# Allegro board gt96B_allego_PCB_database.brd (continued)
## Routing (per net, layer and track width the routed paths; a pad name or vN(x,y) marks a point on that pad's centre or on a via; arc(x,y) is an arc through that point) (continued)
VBATTERY:
  vias: v2(40.59,27.44)
VBUS_USBA_1: length 3.8
  TOP w0.9: 70.85,14.45 70.85,12.73 71.95,11.63 J6.1
VBUS_USBA_2: length 2.1
  TOP w0.9: 51.45,12.73 52.55,11.63 J8.1
1P8_ISET: length 2
  TOP w0.1: v2(41.9,45.75) 42.15,45.5 R145.1 42.15,44.87 U24.C1
1P8_OUT_OCFLAG_N: length 4.2
  TOP w0.1: TP42.1 44.8,41.39 44.8,44.21 U24.A1
5P0V_BOOT: length 5.9
  BOTTOM w0.2: C148.1 v1(65.88,23.19)
  BOTTOM w0.25: U21.1 68.82,21.64 68.37,22.08 67.01,22.08 65.89,23.19 v1(65.88,23.19)
5P0V_COMP: length 2.8
  BOTTOM w0.2: v3(64.72,18.48) U21.6
  BOTTOM w0.35: C151.1 C150.1 63.39,19.09 U21.6
5P0V_EN: length 3.4
  BOTTOM w0.2: U21.3 69.63,19.09 69.43,18.89 v3(69.43,18.48)
  BOTTOM w0.35: U21.3 70.12,19.1 R78.2 R79.1
5P0V_PH:
  vias: v2(63.97,22.59)
5P0V_SENSE: length 3.1
  BOTTOM w0.3: v3(63.1,16.53) 63.35,16.78 63.39,16.78 63.67,17.06 ; 63.67,17.06 R82.1 ; 63.67,17.06 63.92,17.06
  BOTTOM w0.35: R82.1 63.74,17.82 U21.5
5P0V_SS: length 2.4
  BOTTOM w0.2: v3(70.09,16.94) 70.12,16.97 U21.4
  BOTTOM w0.35: U21.4 71.17,17.82 C149.1
+1P1V_SW: length 2.1
  TOP w0.5: L5.1 64.8,38.62 65.67,37.75 v2(65.67,37.59)
+1P8V_BREAKOUT: length 0.8
  TOP w0.25: C144.1 43.64,45.64 U24.B1
  vias: v1(44.03,46.15)
+SYS_DCIN:
  vias: v1(42.91,52.74) v1(42.91,51.81) v1(43.05,51.33) v1(43.09,53.21) v1(43.09,52.28) v1(44.93,52.81) v1(44.91,51.87) v1(45.09,53.28) v1(45.09,52.33) v1(46.91,52.46) v1(46.91,51.53) v1(47.09,52) v1(47.1,51.07) v1(49.47,51.96) v1(49.81,52.34) v1(49.97,51.87) v1(50.31,52.23) v1(59.68,51.79) v1(59.93,51.31) v1(60.18,51.79) v1(60.39,51.13) v1(60.63,51.57) v1(60.9,51.02) v1(61.03,52.45) v1(61.14,52.93) v1(61.14,51.96) v1(61.14,51.46) v1(61.21,50.34) v1(61.44,50.97) v1(61.94,50.96) v1(62.1,50.49) v1(62.44,50.96)
+VDC_IN: length 45.6
  L5 w0.2: v1(65.82,36.79) 65.69,36.66 64.71,36.66 64.1,36.05 60.39,36.05 60.22,36.22 59.85,36.22 59.68,36.05 54.93,36.05 54.5,36.48 52.6,36.48 50.47,34.35 50.47,34.07 49.67,33.27 49.43,33.27 49.33,33.17 49.33,32.75 46.33,29.75 45.07,29.75 44.29,28.97 44.29,27.61 42.81,26.13 39.01,26.13 37.67,24.79 37.55,24.79 37.53,24.77 37.15,24.77 37.13,24.79 32.36,24.79 30.06,22.49 29.74,22.49 v1(29.73,22.49)
  BOTTOM w0.2: v1(29.73,22.49) 29.75,22.5 29.76,22.5 30.08,22.82 J2.37
  BOTTOM w0.3: C129.1 29.78,21.49 29.78,22.44 v1(29.73,22.49)
  vias: v1(72.09,29.78) v1(72.09,28.89) v1(72.34,30.23) v1(72.34,29.35) v1(72.33,28.45) v1(72.57,30.94) v1(72.6,29.78) v1(72.59,28.89) v1(72.85,30.23) v1(72.85,29.33) v1(72.83,28.44) v1(73.1,29.77) v1(73.09,28.89) v1(73.35,30.23) v1(73.35,29.33) v1(73.33,28.42) v1(73.35,31.1) v1(73.6,30.66) v1(73.6,29.77) v1(73.6,28.89) v1(73.85,30.23) v1(73.85,31.09) v1(74.1,30.66) v1(74.1,29.77) v1(74.35,30.21) v1(74.36,31.09) v1(74.6,30.64) v1(74.86,31.09)
+VLDO_SDCARD: length 3.8
  L5 w0.2: v1(6.33,16.29) 6.33,16.3 6.86,16.83 8.06,16.83 8.14,16.91 8.33,16.91 v4(8.45,17.03)
  BOTTOM w0.35: v1(6.33,16.29) 6.33,15.37 6.39,15.31 C120.1
+VRTC: length 25.7
  TOP w0.2: C128.1 24.88,23.2 v1(24.88,22.51) ; R4.1 6.38,23.82 6.13,24.07 6.13,25.96 v1(6.23,26.06)
  L5 w0.2: v1(24.88,22.51) 24.29,22.51 22.59,20.81 19.15,20.81 14.66,25.3 6.74,25.3 6.23,25.81 v1(6.23,26.06)
  BOTTOM w0.2: v1(24.88,22.51) J2.11
+VRTC_R: length 26.8
  TOP w0.2: BT1.1 9.93,24.58 R4.2 6.58,25.55 6.88,25.85 6.88,26.33 4.15,29.06 v1(3.99,29.06) 3.99,35.22 8.64,39.87 BT1.2 10.64,40.57 11.96,40.57 12.31,40.92 CR13.1
+VSYS: length 2
  L5 w0.4: 41.72,32.14 41.22,32.14
  BOTTOM w0.35: v3(40.13,28.2) 41.21,28.2 R33.2
  vias: v1(6.93,42.13) v1(6.93,41.63) v1(7.57,41.51) v1(10.73,46.42) v1(10.97,45.98) v1(13.27,45.98) v1(13.77,45.98) v1(19.06,21.9) v1(19.34,29.61) v1(19.34,29.11) v1(19.34,28.61) v1(19.34,28.11) v1(19.34,27.61) v1(19.34,27.11) v1(19.56,21.9) v1(19.68,21.42) v1(20.06,21.9) v1(20.18,21.42) v1(20.56,21.9) v1(48.04,40.14) v1(48.27,39.67) v1(48.53,40.61) v1(48.53,40.11) v1(48.77,39.67) v1(48.94,40.91) v1(48.97,40.36) v1(49.4,41.16) v1(49.37,40.66) v1(49.9,41.11) v1(50.39,41.27)
BLDRW_0_PWM: length 35.4
  TOP w0.1: J12.28 36,51.09 37.09,50 37.09,46.58 37.69,45.98 37.69,43.31 v1(37.31,42.93)
  BOTTOM w0.1: J3.56 18.18,45.91 19.25,46.98 24.75,46.98 25.29,46.44 27.05,46.44 28.4,45.09 28.4,42.46 30.16,40.7 35.08,40.7 v1(37.31,42.93)
BTN_N: length 29.5
  TOP w0.1: v1(38.95,27.34) 38.99,27.34 39.09,27.44 39.09,27.5 39.35,27.76 39.35,29.41 39.26,29.5 39.26,30.03 39.59,30.36 39.59,35.52 38.91,36.2 38.91,37.66 38.7,37.87 38.7,39.3 39.2,39.8 39.2,40.14 39.02,40.32 39.02,40.57 36.89,42.7 36.89,49.85 35.72,51.02 35.2,51.02 J12.26
  BOTTOM w0.1: v1(38.95,27.34) 38.95,27.23 39.28,26.9 J2.84
CHRG_INT_N: length 23.4
  TOP w0.1: v1(30.48,29.75) 30.48,30.03 29.66,30.86 29.66,32.18 29.47,32.37 29.47,38.31 29.48,38.32 29.48,40.19 29.08,40.59 29.08,41.33 29,41.41 29,43.49 32,46.49 J12.23
  BOTTOM w0.1: v1(30.48,29.75) J2.40
CLK_19P2M: length 2.5
  BOTTOM w0.14: R39.1 36.61,21.44 36.83,21.67 36.83,22.67 36.88,22.72 J2.71
CLK_19P2M_CONN: length 31.8
  TOP w0.14: v1(29.35,16.3) 29.35,15.66 28.44,14.75 27.5,14.75 26.75,14 J13.15
  L3 w0.208: v1(40.19,20.97) 40.19,19.98 40.53,19.64 41.44,19.64 43.54,17.54 43.54,14.64 43.02,14.12 41.97,14.12 39.18,16.91 29.81,16.91 29.35,16.45 v1(29.35,16.3)
  BOTTOM w0.14: R39.2 38.08,20.82 C83.1 38.28,20.82 38.53,21.06 40.1,21.06 v1(40.19,20.97)
CODEC_MCLK: length 1.7
  BOTTOM w0.14: R7.1 31.47,22.01 31.34,22.14 31.34,22.73 31.28,22.79 J2.43
CODEC_MCLK_CONN: length 12.2
  TOP w0.1: v1(32.75,19) 32.75,16.51
  TOP w0.14: J13.17 27.55,14 28,14.45 28.62,14.45 30.01,15.84 32.44,15.84 32.76,16.16 32.76,16.5 32.75,16.51
  BOTTOM w0.14: v1(32.75,19) 32.68,19.07 32.68,19.22 31.77,20.13 31.56,20.13 C7.1 R7.2
DCIN_EN: length 9.4
  BOTTOM w0.1: v1(34.78,15.91) 33.96,16.73 R18.1 R17.2 28.88,16.73 28.02,15.87 28.02,15.39 28.14,15.27 28.14,14.42 28,14.27 28,14.06
DDI1_CTRL_CLK: length 47.2
  TOP w0.1: v1(18.38,30.87) 18.36,30.87 17.88,30.39 17.88,20.62 19.75,18.75 19.75,16.17 20.15,15.77 20.15,12.86 20.55,12.46 v1(20.55,12.42)
  BOTTOM w0.1: U3.31 21.23,13.1 v1(20.55,12.42) 20.55,12.45 R11.2 ; v1(18.38,30.87) 19.29,31.78 34.15,31.78 36.27,29.66 36.27,26.91 36.08,26.72 J2.68
DDI1_CTRL_DAT: length 48.1
  TOP w0.1: v1(20.55,13.03) 20.55,15.66 19.95,16.26 19.95,18.83 18.08,20.71 18.08,30 18.78,30.7 18.78,31.12 18.79,31.13 18.79,31.57 v3(18.38,31.98)
  BOTTOM w0.1: R10.2 20,13.7 20.45,13.7 20.55,13.6 v1(20.55,13.03) 21.02,13.5 U3.32 ; v3(18.38,31.98) 34.23,31.98 36.48,29.73 J2.70
DISPLAY_0_RST_N: length 35.4
  TOP w0.1: J12.30 37.29,51.51 37.29,46.66 38.16,45.79 38.16,43.15 38.33,42.98 38.33,41.97 38.58,41.72 v1(38.58,41.7)
  BOTTOM w0.1: J3.68 20.58,46.54 20.81,46.77 24.67,46.77 25.2,46.24 26.97,46.24 28.2,45.01 28.2,42.38 30.12,40.46 37.34,40.46 v1(38.58,41.7)
DNX_BTN_1P8: length 16.7
  TOP w0.1: SW3.4 SW3.3 v1(48.92,46.92) ; R98.2 v1(44.4,42.72)
  L3 w0.1: v1(48.92,46.92) 48.93,46.92 48.93,44.59 47.06,42.72 v1(44.4,42.72)
EEPROM_E2: length 3.9
  TOP w0.1: v1(34.07,37.28) U14.3
  TOP w0.25: R131.2 R132.1 34.47,40 34.07,39.6 U14.3
EEPROM_VCC: length 2.8
  TOP w0.25: R133.2 36.61,31.54 TP56.1 U14.8
EEPROM_WC_N: length 5.3
  TOP w0.2: U14.7 35.34,35.56 v1(35.2,35.7)
  TOP w0.25: U14.7 35.34,32.18 34.88,31.72 R102.1 R134.2
EN_1P1V: length 3.3
  TOP w0.1: U5.1 59.92,39.11 59.63,39.4 C160.1 59.63,40.61 v2(59.87,40.85) 59.41,41.31 R52.2
EN_3P3V: length 2.5
  TOP w0.2: U27.1 49.41,38.73 C158.1 48.59,38.74 R34.2 v3(47.64,38.73)
EQ: length 2.5
  BOTTOM w0.1: U3.13 30.19,13.1 30.57,13.48 31.32,13.48 31.59,13.21 R16.1 32.19,13.08
FB_1P1V: length 2.1
  TOP w0.2: R53.2 59.48,36.78 59.5,36.8 60.1,36.8 v1(60.1,36.8) 60.1,36.81 60.19,36.9 U5.4
FB_3P3V: length 2.1
  TOP w0.2: R44.2 R45.1 49.9,36.71 49.56,37.06 v1(49.56,37.06) 49.73,37.23 U27.4
FLASH_TORCH: length 31.1
  TOP w0.1: v1(37.91,37.25) 37.9,37.26 37.9,38.21 37.71,38.4 37.71,40.23 37.02,40.92 37.02,41.16 36.59,41.59 35.89,42.29 35.89,45.21 34,47.1 J12.25
  BOTTOM w0.1: J3.75 22.18,40.18 24.62,37.75 29.14,37.75 29.14,37.75 29.48,37.75 29.48,37.75 34.26,37.75 34.36,37.65 37.5,37.65 37.9,37.25 v1(37.91,37.25)
FULLPWRMGMTZ: length 1.6
  TOP w0.1: U2.40 65.71,28.48 R27.2
GANGED: length 1.6
  TOP w0.1: U2.42 64.87,29.48 65.18,29.79 R5.2
GPIO_22: length 29
  TOP w0.1: v3(39.73,29.8) 39.73,30.06 39.92,30.25 39.92,37.9 41.2,39.18 41.2,39.94 41.4,40.14 41.4,41.15 41.2,41.35 41.2,50.93 42,51.73 J12.34
  BOTTOM w0.1: v3(39.73,29.8) 39.76,29.77 40.77,29.77 41.92,28.62 41.92,26.9 41.81,26.79 41.52,26.79 41.28,26.55 J2.94
GRST_N: length 4.1
  TOP w0.1: U2.50 63.45,33.18 63.73,33.45 64.21,33.45 64.83,34.07 64.83,34.2 65.18,34.55 C2.1 65.18,34.78 65.19,34.79 Q1.3 65.19,36.16 v1(65.16,36.19)
HDMI_5V_EN: length 2.5
  BOTTOM w0.1: v2(26.55,3.48) 26.36,3.67 C159.1 ; R146.2 C159.1 ; C159.1 25.61,3.67 U26.4
HDMI_5V_I_ADJ: length 2.2
  BOTTOM w0.1: R143.1 24.89,6.39 v2(24.67,6.61) 24.05,5.99 U26.2
HDMI_5V_OCFLAG_N: length 3.4
  BOTTOM w0.1: R140.2 27.15,4.6 v2(26.64,5.11) 26.56,5.03 R146.1 25.25,5.03 24.7,5.58 U26.3
HDMI_CEXT: length 1.1
  BOTTOM w0.2: U3.17 29.2,11.08 29.56,10.72 C21.1
HDMI_CLK_C_DN: length 0.6
  BOTTOM w0.112: C73.2 28.8,14.38 28.8,14.06
HDMI_CLK_C_DP: length 0.6
  BOTTOM w0.112: C77.2 28.46,14.37 28.39,14.3 28.39,14.07 28.4,14.06
HDMI_CLK_CONN_DN: length 9.9
  TOP w0.112: J10.12 24.16,9.38 24.16,8.51 v1(24.49,8.18)
  L5 w0.076: v1(24.49,8.18) 24.49,8.37 24.71,8.59 24.93,8.59 25.18,8.35 25.25,8.35 25.52,8.07 25.66,8.07 25.93,8.34 26.21,8.34 26.35,8.21 26.46,8.21 26.58,8.33 26.86,8.33 26.99,8.21 27.1,8.21 27.23,8.34 27.64,8.34 28.48,7.5 29.23,7.5 29.74,8.01 29.74,8.33 29.31,8.77 29.04,8.77 v4(29,8.73)
  BOTTOM w0.112: v4(29,8.73) L11.5
HDMI_CLK_CONN_DP: length 9.9
  TOP w0.112: v1(25.07,7.97) 25.15,8.05 25.15,9.37 J10.10
  L5 w0.076: v1(25.07,7.97) 25.18,7.86 25.74,7.86 26.02,8.13 26.12,8.13 26.26,8 26.55,8 26.67,8.12 26.78,8.12 26.9,8 27.19,8 27.32,8.13 27.55,8.13 28.39,7.29 29.32,7.29 29.95,7.92 29.95,8.42 29.39,8.97 28.7,8.97 v4(28.6,8.88)
  BOTTOM w0.112: v4(28.6,8.88) L11.6
HDMI_CLK_DN: length 36
  L3 w0.117: v1(31.73,27.9) 31.73,27.12 31.47,26.86 30.86,26.86 30.43,27.28 30.43,28.46 29.14,29.75 29.14,30.25 29.02,30.37 28.86,30.37 28.74,30.25 28.74,29.06 28.48,28.8 28.04,28.8 27.77,29.06 27.77,30.25 27.66,30.37 27.42,30.37 27.3,30.25 27.3,29.06 27.04,28.8 26.6,28.8 26.34,29.06 26.34,30.25 26.22,30.37 25.33,30.37 22.81,27.85 22.81,24.53 23.79,23.55 23.79,21.79 25.92,19.66 26.31,19.66 28.67,17.3 28.67,16.24 28.83,16.09 v1(28.83,16)
  BOTTOM w0.112: v1(31.73,27.9) 31.61,27.79 31.61,27.45 31.69,27.38 31.69,26.9 31.61,26.82 31.61,26.36 J2.46 ; C73.1 28.87,15.21 28.87,15.97 v1(28.83,16)
HDMI_CLK_DP: length 36
  L3 w0.117: v1(31.13,27.91) 31.48,27.56 31.48,27.22 31.36,27.11 30.96,27.11 30.68,27.39 30.68,28.56 29.39,29.85 29.39,30.36 29.13,30.62 28.75,30.62 28.49,30.36 28.49,29.17 28.37,29.05 28.14,29.05 28.02,29.17 28.02,30.36 27.76,30.62 27.32,30.62 27.05,30.36 27.05,29.17 26.94,29.05 26.7,29.05 26.59,29.17 26.59,30.36 26.32,30.62 25.22,30.62 22.56,27.96 22.56,24.43 23.54,23.45 23.54,21.69 25.82,19.41 26.21,19.41 28.42,17.2 28.42,15.57 v1(28.46,15.53)
  BOTTOM w0.112: v1(31.13,27.91) 31.34,27.7 31.34,26.35 J2.44 ; v1(28.46,15.53) C77.1
HDMI_DAT0_CONN_DN: length 10.8
  TOP w0.112: v1(26.24,7.13) 26.48,7.36 26.48,7.93 25.75,8.65 J10.9
  L5 w0.076: v1(26.24,7.13) 26.36,7.24 26.96,7.24 27.45,6.75 28.17,6.75 28.42,7 28.53,7 28.79,6.75 29.16,6.75 30.22,7.81 30.22,8.53 29.51,9.25 28.28,9.25 28.2,9.18 v4(28.2,9.11)
HDMI_DAT0_CONN_DP: length 10.8
  TOP w0.112: J10.7 26.75,6.9 v1(26.8,6.85)
  L5 w0.076: v1(26.8,6.85) 27.05,6.85 27.36,6.54 29.25,6.54 30.43,7.72 30.43,8.62 29.59,9.46 27.95,9.46 27.85,9.36 v4(27.8,9.36)
HDMI_DAT1_CONN_DN: length 9.6
  TOP w0.112: J10.6 27.25,8.65 27.58,8.32 27.58,7.51 v1(27.41,7.34)
  L5 w0.076: v1(27.41,7.34) 27.23,7.52 26.08,7.52 25.91,7.34 24.38,7.34 23.84,7.88 23.84,8.5 24.72,9.38 26.16,9.38 v4(26.2,9.34)
HDMI_DAT1_CONN_DP: length 9.6
  TOP w0.112: v1(28,7.14) 27.86,7.28 27.86,8.26 28.25,8.65 J10.4
  L5 w0.076: v1(28,7.14) 28,7.29 27.57,7.72 26,7.72 25.82,7.55 24.47,7.55 24.05,7.97 24.05,8.41 24.81,9.17 25.76,9.17 v4(25.8,9.13)
HDMI_DAT2_CONN_DN: length 9.8
  TOP w0.112: J10.3 28.66,9.38 28.66,8.26 v1(28.75,8.17)
  L5 w0.076: v4(25.4,8.87) 25.44,8.83 25.85,8.83 26.05,9.03 26.2,9.03 26.28,8.95 26.28,8.87 26.32,8.83 26.48,8.83 26.61,8.96 26.61,10.32 26.81,10.52 27.19,10.52 27.39,10.32 27.39,8.9 27.47,8.83 27.59,8.83 27.81,9.04 27.92,9.04 28.1,8.86 28.22,8.86 28.29,8.79 28.29,8.69 28.19,8.58 28.19,8.48 28.27,8.4 28.37,8.4 28.59,8.62 28.76,8.62 28.93,8.45 28.93,8.26 28.85,8.17 v1(28.75,8.17)
  BOTTOM w0.112: v4(25.4,8.87) L10.7
HDMI_DAT2_CONN_DP: length 9.8
  TOP w0.112: v1(29.35,8.17) 29.35,8.18 29.75,8.58 J10.1
  L5 w0.076: v4(25.05,8.88) 25.05,8.87 25.3,8.62 26.57,8.62 26.82,8.87 26.82,10.24 26.89,10.31 27.11,10.31 27.18,10.24 27.18,8.82 27.38,8.62 27.75,8.62 28.59,7.78 28.91,7.78 29.3,8.17 v1(29.35,8.17)
  BOTTOM w0.112: v4(25.05,8.88) 25,8.92 L10.8
HDMI_OB_CLK_DN: length 1.2
  BOTTOM w0.112: L11.4 29,10.39 28.94,10.45 28.94,10.9 28.8,11.04 U3.18
HDMI_OB_CLK_DP: length 1.3
  BOTTOM w0.112: U3.19 28.4,11.05 28.66,10.79 28.66,10.46 28.6,10.4 L11.3
HDMI_OB_DAT0_DN: length 1.4
  BOTTOM w0.112: U3.21 27.56,11.3 27.56,11.06 28.2,10.42 L11.2
HDMI_OB_DAT0_DP: length 1.4
  BOTTOM w0.112: U3.22 27.29,11.25 27.29,10.95 27.84,10.39 27.84,10.22 L11.1
HDMI_OB_DAT1_DN: length 1.4
  BOTTOM w0.112: U3.23 26.8,11.2 26.71,11.12 26.71,10.99 26.16,10.43 26.16,10.22 L10.4
HDMI_OB_DAT1_DP: length 1.4
  BOTTOM w0.112: U3.24 26.44,11.3 26.44,11.1 25.84,10.5 25.84,10.22 L10.3
HDMI_OB_DAT2_DN: length 1.3
  BOTTOM w0.112: L10.2 25.36,10.22 25.36,10.44 25.54,10.62 25.54,10.99 25.6,11.05 U3.26
HDMI_OB_DAT2_DP: length 1.3
  BOTTOM w0.112: U3.27 25.2,11.05 25.26,10.99 25.26,10.73 25.04,10.51 25.04,10.22 L10.1
HDMI_OB_HPD_INV: length 9
  TOP w0.1: v1(20.2,11.45) 20.22,11.43 R77.1 CR14.1 20.75,10.81 J10.19
  L5 w0.1: v4(26,11.57) 25.46,12.11 22.8,12.11 22.21,11.52 20.27,11.52 v1(20.2,11.45)
  BOTTOM w0.1: U3.25 v4(26,11.57)
HDMI_OB_SCL: length 12
  TOP w0.1: J10.15 22.75,10.51 23,10.76 v1(23.48,10.76)
  BOTTOM w0.1: 16.02,10.87 16.91,11.76 18.27,11.76 19.53,10.5 23.22,10.5 v1(23.48,10.76) 23.48,11.31 24.07,11.9 U3.28
HDMI_OB_SCL_D: length 1.8
  BOTTOM w0.1: v1(16.98,10.6) 16.49,10.11 R22.1 16.02,10.11 CR4.1
HDMI_OB_SDA: length 12.8
  TOP w0.1: J10.16 22.25,10.61 v1(21.8,11.06)
  BOTTOM w0.1: U3.29 24.19,12.3 22.73,10.84 22.02,10.84 v1(21.8,11.06) 21.61,10.88 19.48,10.88 18.39,11.97 16.06,11.97 14.96,10.87
HDMI_OB_SDA_D: length 1.6
  BOTTOM w0.1: CR5.1 14.96,10.11 R21.1 v1(13.98,10.11)
HDMI_PRE: length 2.6
  BOTTOM w0.1: 32.19,12.27 R20.1 31.59,12.11 31.35,11.87 30.62,11.87 30.19,12.3 U3.15
HDMI_REXT: length 0.9
  BOTTOM w0.1: U3.16 30.17,11.9 30.61,11.46 R37.1
HDMI_TX_0_C_DN: length 0.6
  BOTTOM w0.112: C74.2 27.6,14.36 27.6,14.06
HDMI_TX_0_C_DP: length 0.6
  BOTTOM w0.112: 27.2,14.06 27.19,14.07 27.19,14.36 27.28,14.45 C78.2
HDMI_TX_0_DN: length 36
  L3 w0.117: v1(34.76,27.7) 34.51,27.45 34.51,27.32 34.65,27.18 34.65,27.04 34.54,26.93 34.33,26.93 34.1,27.16 33,27.16 32.26,27.9 32.26,28 31.15,29.11 31.15,30.05 30.06,31.14 25.01,31.14 22.04,28.17 22.04,24.21 23.01,23.24 23.01,21.48 24.74,19.75 24.74,18.82 25.06,18.5 25.36,18.5 25.65,18.79 26.09,18.79 26.51,18.37 26.51,17.98 26.83,17.67 27.21,17.67 27.44,17.44 27.44,16.48 27.53,16.39 27.66,16.39 27.71,16.44 27.85,16.44 27.9,16.39 27.9,15.76 27.68,15.54 v1(27.62,15.54)
  BOTTOM w0.112: C74.1 27.58,15.31 27.58,15.54 v1(27.62,15.54) ; v1(34.76,27.7) 34.82,27.7 34.94,27.59 34.94,26.34 J2.62
HDMI_TX_0_DP: length 36
  L3 w0.117: v1(35.21,28.11) 34.59,28.11 34.31,27.83 34.31,27.73 33.99,27.41 33.1,27.41 32.51,28 32.51,28.1 31.4,29.21 31.4,30.15 30.16,31.39 24.91,31.39 21.79,28.27 21.79,24.11 22.76,23.14 22.76,21.38 24.49,19.65 24.49,18.72 24.96,18.25 25.46,18.25 25.75,18.54 25.99,18.54 26.26,18.27 26.26,17.88 26.72,17.42 27.11,17.42 27.19,17.34 27.19,16.38 27.15,16.33 v1(27.15,15.92)
  BOTTOM w0.112: v1(27.15,15.92) 27.09,15.86 27.09,15.25 C78.1 ; J2.64 35.21,26.36 v1(35.21,28.11)
HDMI_TX_1_C_DN: length 0.6
  BOTTOM w0.112: C75.2 26.72,14.45 26.81,14.36 26.81,14.07 26.8,14.06
HDMI_TX_1_C_DP: length 0.6
  BOTTOM w0.112: 26.4,14.06 26.4,14.36 C79.2
HDMI_TX_1_DN: length 35.9
  L3 w0.117: v1(26.68,15.54) 26.68,15.57 26.57,15.68 26.57,16.09 26.31,16.35 26.06,16.35 25.77,16.64 25.77,16.72 26.04,16.99 26.04,17.36 25.69,17.71 25.32,17.71 24.99,17.38 24.83,17.38 24.32,17.88 24.32,18.15 24.04,18.43 23.82,18.43 23.55,18.7 23.55,18.87 23.57,18.89 23.57,19.83 22.24,21.16 22.24,22.92 21.27,23.89 21.27,28.49 24.69,31.91 30.38,31.91 31.92,30.37 31.92,29.44 32.97,28.39 33.06,28.3 33.06,28.22 33.32,27.95 33.7,27.95 34.06,28.32 v1(34.13,28.32)
  BOTTOM w0.112: v1(26.68,15.54) 26.68,15.1 C75.1 ; v1(34.13,28.32) 34.03,28.22 34.03,26.34 J2.58
HDMI_TX_1_DP: length 35.9
  L3 w0.117: v1(33.53,28.36) 33.72,28.56 33.72,28.76 33.61,28.88 33.39,28.88 33.25,28.74 32.97,28.74 32.17,29.54 32.17,30.47 30.48,32.16 24.59,32.16 21.02,28.59 21.02,23.79 21.99,22.82 21.99,21.06 23.32,19.72 23.32,19 23.3,18.97 23.3,18.6 23.72,18.18 23.94,18.18 24.07,18.04 24.07,17.78 24.72,17.13 25.1,17.13 25.43,17.46 25.59,17.46 25.79,17.26 25.79,17.09 25.52,16.83 25.52,16.54 25.89,16.17 25.89,16.11 v1(26.16,15.84)
  BOTTOM w0.112: J2.56 33.75,26.36 33.75,28.14 v1(33.53,28.36) ; v1(26.16,15.84) C79.1
HDMI_TX_2_C_DN: length 0.6
  BOTTOM w0.112: C76.2 25.54,14.37 25.63,14.28 25.63,14.09 25.6,14.06
HDMI_TX_2_C_DP: length 0.6
  BOTTOM w0.112: C80.2 25.2,14.38 25.2,14.06
HDMI_TX_2_DN: length 36.2
  L3 w0.117: v1(32.72,29.72) 33.07,30.07 33.07,30.32 32.46,30.93 32.46,31.32 32.14,31.64 31.74,31.64 30.7,32.68 24.37,32.68 20.5,28.81 20.5,23.57 21.47,22.6 21.47,19.64 23.77,17.34 23.77,16.87 24.67,15.97 24.84,15.97 25.01,16.14 25.18,16.14 25.42,15.9 25.42,15.63 25.37,15.58 25.37,15.58 v1(25.36,15.58)
  BOTTOM w0.112: v1(25.36,15.58) 25.37,15.58 25.37,15.51 25.54,15.34 C76.1 ; J2.50 32.54,26.35 32.54,28.76 32.83,29.05 32.83,29.62 v1(32.72,29.72)
HDMI_TX_2_DP: length 36.2
  L3 w0.117: v1(24.73,15.52) 24.73,15.55 23.52,16.76 23.52,17.23 21.22,19.54 21.22,22.5 20.25,23.47 20.25,28.91 24.27,32.93 30.8,32.93 31.85,31.89 32.25,31.89 32.71,31.42 32.71,31.03 33.32,30.42 33.32,29.46 v1(33.24,29.38)
  BOTTOM w0.112: C80.1 24.98,15.26 24.73,15.5 v1(24.73,15.52) ; v1(33.24,29.38) 33.24,29.07 32.82,28.65 32.82,26.35 J2.52
HPD_SRC: length 16.6
  TOP w0.1: v1(36.44,15.67) 36.45,15.67 36.45,15.68 36.42,15.68 35.95,16.15 35.95,18.89 35.68,19.16 v1(35.68,22.06)
  BOTTOM w0.1: v1(36.44,15.67) 36.45,15.67 36.45,15.68 36.42,15.68 35.03,17.08 29.98,17.08 29.98,17.08 R136.2 28.35,17.08 Q2.3 ; v1(35.68,22.06) J2.65
HPD_SRC_N: length 7.3
  BOTTOM w0.1: v1(28.27,19) 28.18,18.91 Q2.1 27.02,17.73 R51.1 26.22,17.73 26.21,17.74 26.14,17.67 26.14,16.52 25.74,16.12 25.74,15.7 25.84,15.6 25.84,15.1 25.84,14.43 26,14.27 26,14.06
HS_PIN60_RFU: length 2.3
  TOP w0.1: v2(45.3,19.04) R8.2 J13.60
HUB1_USB2_1_DN: length 34.5
  TOP w0.112: v1(74.67,15.8) 74.87,15.6 U20.A2 ; U2.2 55.6,31.98 55.49,32.09 54.49,32.09 54.25,31.85 53.59,31.85 v1(53.51,31.77)
  L3 w0.117: v1(53.51,31.77) 53.63,31.89 53.96,31.89 54.07,32 55.18,32 55.76,31.42 56.95,31.42 60.96,27.41 60.96,23.75 62.42,22.29 64.85,22.29 66.63,20.51 72.24,20.51 74.67,18.08 74.67,15.8 v1(74.67,15.8)
HUB1_USB2_1_DP: length 34.4
  TOP w0.112: U2.1 55.6,32.48 55.49,32.37 54.61,32.37 54.38,32.37 54.15,32.14 53.95,32.14 v1(53.79,32.3) ; U20.B2 v1(75.27,15.81)
  L3 w0.117: v1(75.27,15.81) 74.92,16.15 74.92,18.19 72.34,20.76 66.73,20.76 64.95,22.54 62.52,22.54 61.21,23.85 61.21,27.51 57.05,31.67 55.86,31.67 55.28,32.25 53.84,32.25 v1(53.79,32.3)
HUB1_USB3_1_RX_DN: length 38.2
  TOP w0.112: v1(77.38,16.04) 77.48,15.94 77.76,15.94 78,15.7 78,15.68 L3.4 ; U2.7 55.6,29.48 55.49,29.59 53.67,29.59 v1(53.44,29.36)
  L3 w0.117: v1(53.44,29.36) 53.7,29.62 54.02,29.62 56.07,27.57 56.7,27.57 57.87,26.4 57.87,23.15 63.47,17.55 65.41,17.55 66.28,16.68 68.72,16.68 71.22,14.18 77.31,14.18 77.84,14.71 77.84,15.33 77.38,15.79 v1(77.38,16.04)
HUB1_USB3_1_RX_DP: length 38.1
  TOP w0.112: L3.3 77.64,15.53 77.64,15.66 77.64,15.67 77.56,15.67 77.51,15.62 77,15.62 v1(76.85,15.76) ; v1(53.42,30.14) 53.69,29.87 55.49,29.87 55.6,29.98 U2.6
  L3 w0.117: v1(76.85,15.76) 77.04,15.57 77.25,15.57 77.59,15.23 77.59,14.81 77.21,14.43 73.24,14.43 73.13,14.55 73.13,14.6 73.01,14.72 72.77,14.72 72.66,14.6 72.66,14.55 72.54,14.43 71.32,14.43 68.82,16.93 66.38,16.93 65.51,17.8 63.57,17.8 58.12,23.25 58.12,26.5 56.8,27.82 56.17,27.82 54.12,29.88 53.7,29.88 53.44,30.14 v1(53.42,30.14)
HUB1_USB3_1_TX_DN: length 0.5
  TOP w0.112: L4.4 73.25,15.63 73.18,15.71 73.26,15.8 C13.2
HUB1_USB3_1_TX_DN_C: length 32.2
  TOP w0.112: U2.4 55.6,30.98 55.49,31.09 54.32,31.09 54.21,30.98 v1(53.58,30.98) ; C13.1 v1(73.76,16.4)
  L3 w0.117: v1(53.58,30.98) 53.83,30.98 53.83,30.98 54.52,30.98 55.86,29.64 56.78,29.64 59.79,26.63 59.79,23.22 62,21.01 64.33,21.01 66.08,19.26 70.03,19.26 71.48,17.81 71.48,16.5 71.99,15.99 72.98,15.99 73.39,16.4 v1(73.76,16.4)
HUB1_USB3_1_TX_DP: length 0.6
  TOP w0.112: L4.3 72.77,15.51 72.84,15.51 72.84,15.65 72.7,15.8 C14.2
HUB1_USB3_1_TX_DP_C: length 32.2
  TOP w0.112: v1(73.22,16.87) 72.74,16.4 C14.1 ; v1(54.02,31.39) 54.04,31.37 55.49,31.37 55.6,31.48 U2.3
  L3 w0.117: v1(54.02,31.39) 54.19,31.39 54.35,31.23 54.62,31.23 55.96,29.89 56.88,29.89 60.04,26.73 60.04,23.32 62.1,21.26 64.43,21.26 66.18,19.51 70.13,19.51 71.73,17.91 71.73,17.88 71.85,17.77 72.23,17.77 72.35,17.65 72.35,17.42 72.23,17.3 71.85,17.3 71.73,17.18 71.73,16.6 72.09,16.24 72.88,16.24 73.22,16.58 v1(73.22,16.87)
HUB2_USB2_1_DN: length 19.2
  TOP w0.112: U2.10 55.6,27.98 55.49,28.09 55.27,28.09 55.07,27.89 53.5,27.89 53.38,28.01 53.12,28 53.02,27.91 v1(52.85,27.91) ; U19.A2 55.4,15.61 v1(55.2,15.81)
  L3 w0.117: v1(52.85,27.91) 52.85,27.68 52.7,27.53 52.5,27.53 51.86,26.89 51.86,18.61 52.13,18.35 52.13,16.96 53.03,16.06 53.25,16.06 53.6,15.71 53.81,15.71 54.16,16.06 54.95,16.06 v1(55.2,15.81)
HUB2_USB2_1_DP: length 19.3
  TOP w0.112: U2.9 55.6,28.48 55.49,28.37 55.16,28.37 54.96,28.17 53.61,28.17 53.35,28.43 v1(53.26,28.43) ; U19.B2 v1(55.8,15.81)
  L3 w0.117: v1(53.26,28.43) 53.26,28.42 53.26,27.74 52.8,27.28 52.6,27.28 52.11,26.79 52.11,18.72 52.38,18.45 52.38,17.06 53.14,16.31 55.29,16.31 55.63,15.97 55.65,15.97 v1(55.8,15.81)
HUB2_USB3_1_RX_DN: length 14.8
  TOP w0.112: v1(58.12,15.71) 58.31,15.71 58.45,15.85 59.97,15.85 60.04,15.78 60.04,15.6 59.93,15.48 L14.4 ; U2.15 55.6,25.48 55.49,25.59 55.33,25.59 55.02,25.29 55.02,25.07 v1(55.2,24.89)
  L3 w0.117: v1(58.12,15.71) 57.92,15.71 55.62,18.01 55.62,20.03 54.8,20.85 54.8,24.52 55.17,24.89 v1(55.2,24.89)
HUB2_USB3_1_RX_DP: length 14.6
  TOP w0.112: v1(57.58,15.46) 57.58,15.46 57.58,15.46 57.74,15.29 58.28,15.29 58.56,15.57 59.25,15.57 L14.3 ; U2.14 55.6,25.98 55.49,25.87 55.22,25.87 v1(54.55,25.21)
  L3 w0.117: v1(57.58,15.46) 57.58,15.46 57.58,15.7 55.37,17.91 55.37,19.93 54.55,20.75 v1(54.55,25.21)
HUB2_USB3_1_TX_DN: length 0.5
  TOP w0.112: L15.4 53.85,15.94 C16.2
HUB2_USB3_1_TX_DN_C: length 13.6
  TOP w0.112: v1(53.94,26.77) 53.94,26.85 54.18,27.09 55.49,27.09 55.6,26.98 U2.12 ; v1(53.86,17.01) C16.1
  L3 w0.117: v1(53.86,17.01) 53.98,17.13 53.98,17.35 53.57,17.76 53.57,17.93 53.84,18.2 53.84,18.37 53.57,18.64 53.57,20.04 53.04,20.56 53.04,22.39 53.4,22.74 53.4,26.15 53.94,26.69 v1(53.94,26.77)
HUB2_USB3_1_TX_DP: length 0.5
  TOP w0.112: L15.3 53.34,15.9 C17.2
HUB3_USB2_1_CONN_DN: length 10.1
  TOP w0.112: L21.B1 49.23,16.45 48.88,16.45 48.77,16.33 48.77,16.19 48.66,16.08 48.43,16.08 48.32,16.19 48.32,16.33 48.21,16.45 47.81,16.45 47.63,16.62 46.27,16.62 44.65,15.01 42.64,15.01 41.98,14.35 41.87,14.35 41.76,14.24 41.76,13.44 J13.53
HUB3_USB2_1_CONN_DP: length 10.2
  TOP w0.112: J13.51 41.34,13.44 41.34,14.21 41.48,14.35 41.48,14.35 41.76,14.62 41.86,14.62 42.52,15.28 44.54,15.28 46.16,16.9 47.75,16.9 47.93,16.72 49.2,16.72 49.27,16.79 L21.A1
HUB3_USB2_1_DN: length 21.2
  TOP w0.112: L21.B2 v1(50.16,16.39) ; U2.18 56.95,23.46 v1(56.95,23.46)
  L3 w0.117: v1(50.16,16.39) 50.53,16.39 52.48,14.43 58.92,14.43 59.37,14.88 59.37,18.43 56.95,20.85 v1(56.95,23.46)
HUB3_USB2_1_DP: length 21.1
  TOP w0.112: U2.17 56.46,24.38 v1(56.46,23.8) ; L21.A2 49.9,16.79 v1(50.11,17)
  L3 w0.117: v1(50.11,17) 50.32,16.79 50.48,16.79 52.59,14.68 58.82,14.68 59.12,14.98 59.12,18.33 56.7,20.75 56.7,23.13 56.46,23.37 v1(56.46,23.8)
HUB3_USB3_1_TX_DP_C: length 13.7
  TOP w0.112: C17.1 v1(53.3,17.23) ; U2.11 55.6,27.48 55.49,27.37 v1(53.88,27.37)
  L3 w0.117: v1(53.3,17.23) 53.32,17.24 53.32,19.93 52.79,20.46 52.79,22.49 53.15,22.85 53.15,26.25 53.53,26.63 53.53,27.01 v1(53.88,27.37)
HUB4_USB2_1_DN: length 1.8
  TOP w0.1: TP65.1 60.36,22.95 60.36,24.3 U2.25
HUB4_USB2_1_DP: length 1.7
  TOP w0.1: U2.24 60.03,24.31 60.03,22.83 TP64.1
HUB_XI: length 7
  TOP w0.201: Y1.1 56.59,38.62 56.88,38.62 57.08,38.42 57.08,37.19 C3.1 57.08,36.84 R29.1 57.17,36.11 57.17,35.9 57.55,35.52 57.55,33.41 57.45,33.31 U2.62
HUB_XO: length 7.3
  TOP w0.201: Y1.3 58.19,39.72 57.39,38.92 57.39,37.44 57.5,37.33 C12.1 57.5,36.75 57.75,36.5 57.75,36.29 R29.2 57.85,36.19 57.85,33.42 57.95,33.32 U2.61
HW_RST_N: length 3.1
  TOP w0.1: J12.6 v1(14,50.82)
  BOTTOM w0.1: v1(14,50.82) 14,51.5 R137.1
I2C_0_SCL: length 26.9
  TOP w0.1: v1(39.17,19.42) 39.29,19.54 39.29,21.11 39.55,21.37 40.55,21.37 40.7,21.23 41.94,21.23 42.15,21.43 42.15,22.49 40.51,24.13 39.42,24.13 38.48,25.07 38.48,26.1 34.07,30.51 R141.1
  BOTTOM w0.1: J2.57 34.08,21.71 34.53,21.26 34.53,20.16 36.09,18.6 38.35,18.6 v1(39.17,19.42)
I2C_0_SCL_EE_R: length 2.8
  TOP w0.1: R141.2 TP68.1 U14.6
I2C_0_SDA: length 14.5
  TOP w0.1: R142.2 33.6,30.32 33.97,30.32 38.28,26.02 38.28,24.99 39.34,23.93 40.43,23.93 41.8,22.56 41.8,22.18 41.68,22.06 v3(41.68,21.91)
  BOTTOM w0.1: v3(41.68,21.91) J2.95
I2C_0_SDA_EE_R: length 3
  TOP w0.1: U14.5 TP57.1 33.26,31.88 R142.1
I2C_1_SCL: length 38.5
  TOP w0.1: v1(19.75,39.51) 19.98,39.51 21.95,37.54 21.95,37.28 21.97,37.26 21.97,22.52 22.19,22.3 22.19,21.29 24.08,19.4 29.62,19.4 29.85,19.17 31.6,19.17 31.89,19.47 32.23,19.47 32.3,19.4 32.92,19.4 33.15,19.17 J13.32
  BOTTOM w0.1: v1(19.75,39.51) 17.96,39.51 16.57,40.9 16.33,40.9 15.78,41.45 J3.43
I2C_1_SDA: length 39.5
  TOP w0.1: J13.34 33.95,18.92 33.27,19.6 32.38,19.6 32.31,19.67 31.81,19.67 31.52,19.37 29.93,19.37 29.7,19.6 24.16,19.6 22.39,21.37 22.39,22.38 22.17,22.6 22.17,37.35 22.15,37.37 22.15,37.73 21.77,38.11 21.77,38.44 21.77,38.89 v1(21.56,39.09)
  BOTTOM w0.1: J3.45 16.18,41.33 16.41,41.1 16.65,41.1 17.98,39.77 19.35,39.77 19.56,39.98 20.68,39.98 v1(21.56,39.09)
I2C_2_SCL: length 56.1
  TOP w0.1: v1(12.72,46.34) 12.51,46.55 11.4,46.55 11.29,46.66 11.29,48.89 11.38,48.98 18.64,48.98 18.78,48.84 18.78,46.09 20.05,44.81 v2(20.05,43.62) 21.11,42.56 21.11,39.94 21.37,39.69 21.53,39.69 21.97,39.25 21.97,38.36 21.97,38.19 22.35,37.81 22.35,37.45 22.37,37.43 22.37,22.69 22.59,22.47 22.59,21.45 24.24,19.8 29.79,19.8 30.01,19.57 31.43,19.57 31.73,19.87 32.39,19.87 32.46,19.8 33.48,19.8 34.04,19.24 34.04,19.11 34.75,18.4 J13.36
  BOTTOM w0.1: J3.28 12.58,46.2 v1(12.72,46.34)
I2C_2_SDA: length 56.6
  TOP w0.1: J13.38 35.55,18.4 v2(33.95,20) 32.54,20 32.47,20.07 31.65,20.07 31.35,19.77 30.09,19.77 29.87,20 24.33,20 22.79,21.54 22.79,22.55 22.57,22.77 22.57,37.51 22.55,37.53 22.55,37.89 22.17,38.27 22.17,39.34 21.62,39.89 21.45,39.89 21.31,40.03 21.31,43.84 18.98,46.17 18.98,48.93 18.73,49.18 11.31,49.18 11.29,49.17 11.09,48.98 11.09,46.58 11.63,46.04 v1(12.02,46.04)
  BOTTOM w0.1: v1(12.02,46.04) 12.18,45.88 J3.26
I2S_1_CLK: length 40.7
  TOP w0.1: v3(30.33,22.09) 30.34,22.08 30.4,22.08 30.68,21.8 31.77,21.8 32.17,22.2 32.17,23.86 32.28,23.97 32.28,24.45 32.48,24.65 32.48,27.15 32.13,27.5 30.87,27.5 30.67,27.69 30.67,28.37 30.4,28.64 28.71,30.33 28.71,38.12 29.08,38.49 29.08,40.03 28.48,40.63 28.48,41.08 28.4,41.16 28.4,43.74 30.91,46.25 30.91,49.22 29.56,50.57 27.15,50.57 26,51.72 J12.18
  BOTTOM w0.1: v3(30.33,22.09) 30.48,22.24 J2.39
I2S_1_FS: length 39
  TOP w0.1: v1(31.77,22.46) 31.78,22.47 31.78,24.98 31.68,25.07 31.68,25.57 31.23,26.02 31.23,26.85 30.47,27.61 30.47,28.28 28.51,30.25 28.51,38.2 28.88,38.57 28.88,39.95 28.28,40.55 28.28,41 28.2,41.08 28.2,43.82 28.4,44.02 v2(28.4,44.89) 29.13,44.89 30.71,46.47 30.71,49.14 29.48,50.37 25.35,50.37 24,51.72 J12.16
  BOTTOM w0.1: v1(31.77,22.46) 31.75,22.46 31.68,22.54 J2.45
I2S_1_RXD: length 38.3
  TOP w0.1: v3(32.08,21.24) 32.56,21.24 32.95,21.64 32.95,21.96 32.57,22.34 32.57,23.69 32.68,23.8 32.68,24.29 32.88,24.49 32.88,27.31 32.33,27.86 32.33,28.15 31.98,28.5 31.08,29.4 31.08,29.46 30.88,29.66 30.88,29.92 29.86,30.94 29.86,32.27 29.67,32.45 29.67,38.23 29.68,38.24 29.68,40.28 29.28,40.68 29.28,41.41 29.2,41.49 29.2,43.41 31.57,45.77 31.97,45.77 32.71,46.52 32.71,48.89 32.65,48.95 32.65,49.14 30,51.79 J12.22
  BOTTOM w0.1: J2.47 32.08,22.76 32.18,22.66 32.18,22.04 32.08,21.94 v3(32.08,21.24)
I2S_1_TXD: length 37.3
  TOP w0.1: v1(32.52,21.83) 32.48,21.86 32.48,22.06 32.37,22.17 32.37,23.77 32.48,23.88 32.48,24.37 32.68,24.57 32.68,27.23 32.13,27.78 32.13,28.07 31.9,28.3 31.57,28.63 30.69,28.63 29.19,30.13 v2(29.19,31.99) 29.07,32.11 29.07,37.02 28.91,37.18 28.91,38.04 29.28,38.41 29.28,40.11 28.68,40.71 28.68,41.16 28.6,41.24 28.6,43.66 31.11,46.17 31.11,49.31 29.65,50.77 28.97,50.77 28.02,51.72 28.02,52.2 J12.20
  BOTTOM w0.1: J2.49 32.48,22.77 32.57,22.68 32.57,21.88 v1(32.52,21.83)
INTD_DSI_TE_1: length 28.5
  TOP w0.1: J12.29 38,47.29 39.05,46.24 v3(39.05,43.34)
  BOTTOM w0.1: v3(39.05,43.34) 39.05,41.27 38.04,40.26 30.04,40.26 28,42.3 28,44.92 26.88,46.04 25.12,46.04 24.59,46.58 23.57,46.58 23.22,46.23 23.22,45.69 23.38,45.53 J3.82
ISH_GPIO_0: length 65.6
  TOP w0.1: R49.1 66.88,11.01 64.09,11.01 59.84,6.76 56.38,6.76 v1(56.14,6.52)
  BOTTOM w0.1: v1(56.14,6.52) 55.67,6.05 49.06,6.05 46.28,3.27 36.11,3.27 33.64,5.74 33.64,9.63 34.81,10.8 34.81,12.57 35.57,13.33 37.54,13.33 38.04,13.83 38.04,16.08 36.01,18.11 31.58,18.11 30.02,19.67 29.95,19.67 28.68,20.94 28.68,21.01 27.88,21.81 27.88,22.39 27.68,22.59 J2.25
ISH_GPIO_0_R: length 1.4
  TOP w0.1: Q3.5 R49.2
ISH_GPIO_1: length 66.1
  TOP w0.1: R50.1 67.49,11.21 63.81,11.21 59.73,7.13 v1(54.4,7.13)
  BOTTOM w0.1: J2.27 28.08,21.9 28.88,21.1 28.88,21.03 30.03,19.87 30.1,19.87 31.67,18.31 35.14,18.31 35.14,18.31 36.09,18.31 38.24,16.16 38.24,13.75 37.62,13.13 35.65,13.13 35.01,12.49 35.01,10.72 33.84,9.55 33.84,5.82 36.19,3.47 46.2,3.47 49,6.27 53.54,6.27 v1(54.4,7.13)
ISH_GPIO_1_R: length 4
  TOP w0.1: R50.2 68.62,9.31 68.62,7.82 68.2,7.4 67.99,7.4 67.42,6.83 Q3.2
ISH_GPIO_2: length 91.9
  TOP w0.1: v1(57.83,5.81) 58,5.98 60.09,5.98 63.42,9.31 R47.1
  BOTTOM w0.1: J2.32 28.88,27.16 28.57,27.46 28.57,28.64 27.21,30.01 19.17,30.01 18.18,29.01 18.18,21.54 19.55,20.17 26.36,20.17 27.36,21.17 28.24,21.17 28.48,20.93 28.48,20.86 29.87,19.47 29.94,19.47 31.5,17.91 35.93,17.91 37.84,16 37.84,13.92 37.45,13.53 35.48,13.53 34.61,12.66 34.61,10.88 33.44,9.71 33.44,5.64 36.01,3.07 46.37,3.07 49.11,5.81 v1(57.83,5.81)
ISH_GPIO_2_R: length 1
  TOP w0.1: R47.2 65.01,9.32 Q4.2
ISH_GPIO_3: length 93.7
  TOP w0.1: v1(54.65,5.26) 55.97,5.26 57.1,6.39 59.98,6.39 63.71,10.12 R48.1
  BOTTOM w0.1: v1(54.65,5.26) 54.32,5.59 49.17,5.59 46.45,2.87 35.92,2.87 33.24,5.55 33.24,9.8 34.41,10.97 34.41,12.74 35.4,13.73 37.37,13.73 37.64,14 37.64,15.92 35.85,17.71 31.42,17.71 29.85,19.27 29.78,19.27 28.28,20.78 28.28,20.85 28.16,20.97 27.46,20.97 26.46,19.97 19.47,19.97 17.98,21.46 17.98,29.09 19.09,30.21 27.29,30.21 29,28.5 29,27.32 29.21,27.11 29.21,26.8 29.28,26.73 J2.34
ISH_GPIO_3_R: length 5.3
  TOP w0.1: Q4.5 65.01,7.21 65.25,7.45 65.76,7.45 66.22,7.91 66.22,9.66 65.76,10.12 R48.2
ISH_GPIO_4: length 44.8
  TOP w0.1: v1(27.78,41.49) 27.78,41.21 28.08,40.91 28.08,30.11 30.07,28.12 30.07,27.45 30.83,26.69 30.83,25.86 31.28,25.41 31.28,23.79 30.69,23.2 29.29,23.2 29,22.91 28.71,22.91 28.48,22.68 v1(28.48,22.06) ; v1(38.8,39.97) 38.8,40.51 36.69,42.62 36.69,47.09 J12.27
  BOTTOM w0.1: v1(27.78,41.49) 29.31,39.97 v1(38.8,39.97) ; v1(28.48,22.06) J2.29
ISH_GPIO_5: length 32.3
  TOP w0.1: v1(27.68,36.22) 27.68,29.94 v1(29.4,28.22) ; v1(31.51,36.46) 31.11,36.86 31.11,41.07 31.3,41.26 31.36,41.26 31.5,41.4 31.5,45.03 32.91,46.44 32.91,48.98 32.85,49.04 32.85,49.22 32.51,49.56 32.51,51.23 32,51.74 J12.24
  BOTTOM w0.1: v1(27.68,36.22) 31.27,36.22 v1(31.51,36.46) ; v1(29.4,28.22) 29.92,28.22 30.15,27.99 30.15,26.8 30.08,26.73 J2.38
ISH_GPIO_6: length 40.7
  TOP w0.1: v1(28.88,22.51) 29.35,22.98 30.76,22.98 31.58,23.8 31.58,24.89 31.48,24.99 31.48,25.49 31.03,25.94 31.03,26.77 30.27,27.53 30.27,28.2 28.31,30.16 28.31,38.28 28.48,38.45 v1(28.48,39.78) ; J12.31 v3(40,42.01)
  BOTTOM w0.1: v1(28.48,39.78) 28.76,39.5 38.99,39.5 39.27,39.78 39.27,41.28 v3(40,42.01) ; v1(28.88,22.51) J2.31
ISH_I2C_0_SCL: length 23.7
  TOP w0.1: J12.15 24,47.26 25.38,45.88 25.38,43.55 23.58,41.75 23.58,41.25 23.78,41.05 23.78,31.44 v3(25.64,29.58)
  BOTTOM w0.1: J2.16 25.68,29.54 v3(25.64,29.58)
ISH_I2C_0_SDA: length 23.8
  TOP w0.1: v3(26.08,28) 26.56,28.48 26.56,28.91 26.11,29.36 26.11,29.77 23.98,31.9 23.98,41.13 23.78,41.33 23.78,41.67 25.58,43.47 25.58,45.75 26,46.17 J12.17
  BOTTOM w0.1: J2.18 26.08,27.02 26.01,27.09 26.01,27.93 v3(26.08,28)
ISH_I2C_1_SCL: length 31.3
  TOP w0.1: J12.19 28,46.29 26.58,44.87 26.58,41.33 26.81,41.1 27.08,41.1 27.68,40.5 27.68,37.07 27.08,36.47 27.08,35.97 27.28,35.77 27.28,29.78 28.8,28.25 28.8,27.97 28.88,27.89 28.88,25.48 28.43,25.03 28.43,24.44 27.15,23.15 27.15,22.13 26.54,21.52 v3(26.54,21.52)
  BOTTOM w0.1: J2.21 26.88,22.34 26.54,22 v3(26.54,21.52)
ISH_I2C_1_SDA: length 31.1
  TOP w0.1: J12.21 30,47.3 29.08,46.38 28.43,46.38 27.38,45.33 27.38,41.33 27.88,40.83 27.88,36.99 27.28,36.39 27.28,36.05 27.48,35.85 27.48,29.86 29,28.34 29,28.05 29.08,27.97 29.08,25.4 28.63,24.95 28.63,24.35 27.35,23.07 v1(27.35,21.64)
  BOTTOM w0.1: v1(27.35,21.64) 27.28,21.71 J2.23
ISH_UART_0_CTS: length 35.6
  TOP w0.1: J13.2 21.15,19.28 21.79,19.92 21.79,22.14 21.57,22.36 21.57,23.53 21.32,23.79 21.32,33.92 19.95,35.29 v1(19.95,35.61)
  BOTTOM w0.1: J3.9 8.98,41.84 9.18,41.64 9.18,41.3 9.18,41.3 9.18,37.54 10.67,36.05 14.37,36.05 14.66,36.34 19.41,36.34 19.95,35.79 v1(19.95,35.61)
ISH_UART_0_RTS: length 36.7
  TOP w0.1: v1(21.08,36.85) 21.59,36.34 21.59,23.99 21.77,23.81 21.77,22.44 21.99,22.22 21.99,19.83 21.95,19.79 J13.4
  BOTTOM w0.1: J3.11 9.38,41.72 9.38,41.72 9.38,41.22 9.38,41.22 9.38,37.62 10.75,36.25 14.29,36.25 14.57,36.53 20.77,36.53 v1(21.08,36.85)
LED0_A: length 1.9
  TOP w0.35: CR15.2 v1(68.07,0.88)
  BOTTOM w0.35: R93.2 v1(68.07,0.88)
LED0_C: length 3.6
  TOP w0.3: CR15.1 67.84,3.36 67.84,4.05 68.14,4.34 v1(68.14,4.71)
  TOP w0.35: v1(68.14,4.71) 68.14,5.71 68.07,5.78 Q3.3
LED1_A: length 2
  TOP w0.35: CR16.2 v3(66.87,0.87)
  BOTTOM w0.35: R95.2 v3(66.87,0.87)
LED1_C: length 6.1
  TOP w0.3: CR16.1 66.64,3.36 66.64,4.15 v2(67.1,4.61) 66.8,4.91 66.64,4.91 66.27,5.28 66.27,7.48 66.77,7.98 Q3.6
LED2_A: length 1.9
  TOP w0.3: v1(65.67,0.88) CR17.2
  BOTTOM w0.35: R94.2 v1(65.67,0.88)
LED2_C: length 3.6
  TOP w0.3: v2(65.47,4.78) 65.44,4.75 65.44,3.36 CR17.1
  TOP w0.35: Q4.6 65.66,5.18 65.47,4.99 v2(65.47,4.78)
LED3_A: length 2
  TOP w0.3: v3(64.47,0.87) CR18.2
  BOTTOM w0.35: R96.2 v3(64.47,0.87)
LED3_C: length 6.1
  TOP w0.3: 64.47,5.01 64.47,4.99 ; 64.47,4.99 64.24,4.76 64.24,3.36 CR18.1 ; 64.47,4.99 v1(64.46,4.99)
  TOP w0.35: Q4.3 63.52,7.45 63.52,5.96 64.47,5.01
LS_CFG: length 8.5
  L5 w0.1: v4(28,11.57) 28.3,11.87 29.68,11.87 30.27,11.28 30.27,10.7 30.95,10.02 30.95,9.16 30.92,9.13 v1(30.92,9.07)
  BOTTOM w0.1: v1(30.92,9.07) 30.92,9.81 31.76,10.65 R14.1 32.19,11.46 ; U3.20 v4(28,11.57)
LS_PD_N: length 2.4
  BOTTOM w0.1: 32.19,13.89 31.4,13.89 v2(31.29,14) 31.06,13.77 30.44,13.77 30.17,13.5 U3.12
MDSI_A_CLK_CONN_DN: length 55.2
  TOP w0.112: J13.23 29.95,14.31 v1(30.24,14.6)
  L3 w0.117: v1(11.86,38.27) 11.8,38.33 11.8,38.43 12.02,38.43 12.56,38.97 14.28,38.97 15.04,38.21 15.39,37.86 15.39,36.93 15.78,36.54 15.78,35.93 15,35.15 15,33.79 14.88,33.68 13.37,33.68 13.11,33.41 13.11,32.97 13.37,32.71 14.88,32.71 15,32.59 15,32.36 14.88,32.24 13.37,32.24 13.11,31.98 13.11,31.54 13.37,31.27 14.88,31.27 15,31.16 15,30.92 14.88,30.81 13.37,30.81 13.11,30.54 13.11,30.1 13.37,29.84 14.88,29.84 15,29.72 15,29.49 14.88,29.37 13.37,29.37 13.11,29.11 13.11,28.67 13.37,28.4 14.88,28.4 15,28.28 15,27.55 16.77,25.79 16.77,21.99 22,16.76 22,15.55 23.86,13.69 29.51,13.69 29.77,13.95 29.77,14.22 29.89,14.34 29.98,14.34 v1(30.24,14.6)
  BOTTOM w0.112: L19.5 11.55,38.58 v1(11.86,38.27)
MDSI_A_CLK_CONN_DP: length 55.1
  TOP w0.112: v1(29.52,14.6) 29.52,14.37 29.15,14 J13.21
  L3 w0.117: v1(11.26,38.2) 11.41,38.35 11.41,38.4 11.69,38.68 11.92,38.68 12.46,39.22 14.38,39.22 15.64,37.96 15.64,37.03 16.03,36.64 16.03,35.83 15.25,35.05 15.25,33.69 14.99,33.43 13.48,33.43 13.36,33.31 13.36,33.08 13.48,32.96 14.99,32.96 15.25,32.7 15.25,32.26 14.99,31.99 13.48,31.99 13.36,31.87 13.36,31.64 13.48,31.52 14.99,31.52 15.25,31.26 15.25,30.82 14.99,30.56 13.48,30.56 13.36,30.44 13.36,30.2 13.48,30.09 14.99,30.09 15.25,29.82 15.25,29.38 14.99,29.12 13.48,29.12 13.36,29 13.36,28.77 13.48,28.65 14.99,28.65 15.25,28.39 15.25,27.66 17.02,25.89 17.02,22.09 22.25,16.86 22.25,15.65 23.96,13.94 29.41,13.94 29.52,14.06 v1(29.52,14.6)
  BOTTOM w0.112: L19.6 11.15,38.31 v1(11.26,38.2)
MDSI_A_CLK_DN: length 2.9
  BOTTOM w0.112: L19.4 11.55,40.04 11.49,40.11 11.49,40.24 12.46,41.22 12.46,41.33 12.52,41.39 12.52,41.71 12.58,41.78 J3.27
MDSI_A_CLK_DP: length 2.9
  BOTTOM w0.112: L19.3 11.15,40.04 11.21,40.11 11.21,40.36 12.19,41.33 12.19,41.45 12.24,41.5 12.24,41.71 12.18,41.78 J3.25
MDSI_A_DATA_0_CONN_DN: length 55
  TOP w0.112: J13.29 v1(32.35,14.6)
  L3 w0.117: v1(10.24,37.76) 10.57,37.76 11.05,37.28 11.8,37.28 12.13,37.61 12.85,38.33 14.01,38.33 14.74,37.6 14.74,36.67 15.1,36.31 15.1,36.16 14.36,35.42 14.36,34.46 14.22,34.32 13.71,34.32 13.59,34.44 13.59,34.91 13.33,35.17 12.73,35.17 12.47,34.91 12.47,28.4 13.11,27.76 13.88,27.76 16.13,25.51 16.13,21.72 21.35,16.5 21.35,15.29 23.6,13.04 33.6,13.04 33.86,13.3 33.86,13.93 33.6,14.19 33.23,14.19 32.95,13.91 32.06,13.91 31.94,14.03 31.94,14.19 v1(32.35,14.6)
  BOTTOM w0.112: v1(10.24,37.76) 10.24,38.44 10.35,38.55 L19.8
MDSI_A_DATA_0_CONN_DP: length 55.1
  TOP w0.112: v1(31.68,14.6) 31.68,14.53 31.55,14.4 J13.27
  L3 w0.117: v1(31.68,14.6) 31.68,14.53 31.55,14.4 31.55,14.22 31.43,14.1 31.09,14.1 30.96,13.97 30.96,13.83 31.13,13.66 33.05,13.66 33.33,13.94 33.5,13.94 33.61,13.82 33.61,13.41 33.5,13.29 23.7,13.29 21.6,15.39 21.6,16.6 16.38,21.82 16.38,25.62 13.98,28.01 13.21,28.01 12.72,28.5 12.72,34.8 12.84,34.92 13.23,34.92 13.34,34.8 13.34,34.33 13.61,34.07 14.33,34.07 14.61,34.35 14.61,35.32 15.35,36.06 15.35,36.41 14.99,36.77 14.99,37.7 14.12,38.58 12.74,38.58 12.27,38.1 12.27,38.1 12.03,37.86 12.03,37.86 11.7,37.53 11.15,37.53 10.65,38.03 v1(10.65,38.2)
  BOTTOM w0.112: L19.7 10.75,38.3 v1(10.65,38.2)
MDSI_A_DATA_0_DN: length 2.8
  BOTTOM w0.112: J3.19 10.98,41.78 11.04,41.71 11.04,41.56 10.99,41.5 10.99,41.33 10.41,40.76 10.41,40.11 10.35,40.04 L19.1
MDSI_A_DATA_0_DP: length 2.8
  BOTTOM w0.112: L19.2 10.75,40.04 10.69,40.11 10.69,40.64 11.26,41.22 11.26,41.39 11.32,41.44 11.32,41.71 11.38,41.78 J3.21
MDSI_A_DATA_1_CONN_DN: length 55
  TOP w0.112: J13.35 v1(34.75,14.6)
  L3 w0.117: v1(34.75,14.6) 34.98,14.37 34.98,13.54 35.1,13.43 35.26,13.43 35.38,13.54 35.38,13.92 35.64,14.18 36.02,14.18 36.28,13.92 36.28,12.65 36.02,12.39 23.34,12.39 20.7,15.03 20.7,16.24 15.48,21.45 15.48,25.24 13.6,27.12 12.84,27.12 11.83,28.13 11.83,28.54 11.59,28.77 11.59,29.16 11.82,29.39 11.82,29.58 11.59,29.81 11.59,30.21 11.83,30.45 11.83,30.63 11.59,30.87 11.59,31.27 11.82,31.5 11.82,31.69 11.59,31.92 11.59,32.3 11.83,32.54 11.83,32.72 11.61,32.94 11.61,33.34 11.83,33.56 11.83,33.75 11.59,33.99 11.59,34.38 11.83,34.62 11.83,34.8 11.68,34.95 11.68,35.3 12.25,35.87 13.9,35.87 14.22,36.19 14.22,36.28 14.09,36.41 14.09,37.34 13.97,37.46 v1(12.76,37.46)
  BOTTOM w0.112: L18.8 12.75,38.48 12.81,38.41 12.81,38.27 12.74,38.2 12.74,37.48 v1(12.76,37.46)
MDSI_A_DATA_1_CONN_DP: length 55
  TOP w0.112: J13.33 v1(33.95,14.6)
  L3 w0.117: v1(13.15,37.92) 13.38,37.92 13.59,37.71 14.08,37.71 14.34,37.45 14.34,36.51 14.47,36.39 14.47,36.08 14,35.62 12.36,35.62 11.93,35.2 11.93,35.05 12.08,34.9 12.08,34.52 11.84,34.28 11.84,34.09 12.08,33.86 12.08,33.46 11.86,33.24 11.86,33.04 12.08,32.83 12.08,32.44 11.84,32.2 11.84,32.02 12.07,31.79 12.07,31.4 11.84,31.17 11.84,30.97 12.08,30.74 12.08,30.35 11.84,30.11 11.84,29.91 12.07,29.68 12.07,29.29 11.84,29.06 11.84,28.88 12.08,28.64 12.08,28.24 12.95,27.37 13.71,27.37 15.73,25.34 15.73,21.56 20.95,16.34 20.95,15.13 23.44,12.64 35.91,12.64 36.03,12.76 36.03,13.81 35.91,13.93 35.75,13.93 35.63,13.81 35.63,13.44 35.37,13.18 34.38,13.18 34.26,13.29 34.26,13.6 34.38,13.72 34.56,13.72 34.68,13.84 34.68,14.09 34.17,14.6 v1(33.95,14.6)
  BOTTOM w0.112: v1(13.15,37.92) 13.09,37.98 13.09,38.41 13.15,38.48 L18.7
MDSI_A_DATA_1_DN: length 2.8
  BOTTOM w0.112: J3.31 13.38,41.78 13.44,41.71 13.44,41.47 13.39,41.42 13.39,41.33 12.81,40.76 12.81,40.11 12.75,40.04 L18.1
MDSI_A_DATA_1_DP: length 2.8
  BOTTOM w0.112: L18.2 13.15,40.04 13.09,40.11 13.09,40.64 13.66,41.22 13.66,41.3 13.72,41.36 13.72,41.71 13.78,41.78 J3.33
MDSI_A_DATA_2_CONN_DN: length 55.2
  TOP w0.112: J13.41 v1(37.15,14.6)
  L3 w0.117: v1(13.07,36.9) 13.12,36.85 13.12,36.56 13.07,36.51 11.99,36.51 11.04,35.57 11.04,35.05 10.92,34.93 10.62,34.93 10.36,34.67 10.36,34.23 10.62,33.96 10.83,33.96 10.95,33.85 10.95,33.61 10.83,33.5 10.62,33.5 10.36,33.23 10.36,32.79 10.62,32.53 10.83,32.53 10.95,32.41 10.95,32.18 10.83,32.06 10.62,32.06 10.36,31.8 10.36,31.36 10.62,31.09 10.83,31.09 10.95,30.98 10.95,30.74 10.83,30.62 10.62,30.62 10.36,30.36 10.36,29.92 10.62,29.66 10.83,29.66 10.95,29.54 10.95,28.1 12.58,26.48 13.33,26.48 14.84,24.97 14.84,21.18 20.05,15.98 20.05,14.77 23.08,11.74 36.53,11.74 37.15,12.36 v1(37.15,14.6)
  BOTTOM w0.112: v1(13.07,36.9) 13.61,37.44 13.61,38.41 13.55,38.48 L18.6
MDSI_A_DATA_2_CONN_DP: length 55.1
  TOP w0.112: J13.39 v1(36.35,14.6)
  L3 w0.117: v1(13.68,36.93) 13.68,36.77 13.17,36.26 12.09,36.26 11.29,35.46 11.29,34.95 11.02,34.68 10.73,34.68 10.61,34.57 10.61,34.33 10.73,34.21 10.93,34.21 11.2,33.95 11.2,33.51 10.93,33.25 10.73,33.25 10.61,33.13 10.61,32.9 10.73,32.78 10.93,32.78 11.2,32.51 11.2,32.07 10.93,31.81 10.73,31.81 10.61,31.69 10.61,31.46 10.73,31.34 10.93,31.34 11.2,31.08 11.2,30.64 10.93,30.37 10.73,30.37 10.61,30.26 10.61,30.02 10.73,29.91 10.93,29.91 11.2,29.64 11.2,28.21 12.68,26.73 13.44,26.73 15.09,25.07 15.09,21.29 20.3,16.08 20.3,14.87 23.18,11.99 36.43,11.99 36.9,12.46 36.9,12.67 36.68,12.89 36.68,13.12 36.9,13.34 36.9,13.52 36.68,13.74 36.68,13.91 36.9,14.13 36.9,14.27 36.57,14.6 v1(36.35,14.6)
  BOTTOM w0.112: L18.5 13.95,38.48 13.89,38.41 13.89,37.14 v1(13.68,36.93)
MDSI_A_DATA_2_DN: length 2.9
  BOTTOM w0.112: L18.3 13.55,40.04 13.61,40.11 13.61,40.36 14.59,41.33 14.59,41.5 14.64,41.56 14.64,41.71 14.58,41.78 J3.37
MDSI_A_DATA_2_DP: length 2.9
  BOTTOM w0.112: L18.4 13.95,40.04 13.89,40.11 13.89,40.24 14.86,41.22 14.86,41.39 14.92,41.44 14.92,41.71 14.98,41.78 J3.39
MDSI_A_DATA_3_CONN_DN: length 46
  TOP w0.112: J13.47 v1(39.55,14.6)
  L3 w0.117: v1(16.15,37.86) 17.41,36.6 17.41,22.26 22.65,17.02 22.65,15.81 24.12,14.34 28.69,14.34 29.67,15.33 31.66,15.33 31.94,15.61 32.4,15.61 32.63,15.83 33.47,15.83 34.3,15.01 37.76,15.01 38.58,14.19 38.92,14.19 39.33,14.6 v1(39.55,14.6)
  BOTTOM w0.112: L20.6 16.15,38.48 16.21,38.41 16.21,38.27 16.15,38.21 v1(16.15,37.86)
MDSI_A_DATA_3_CONN_DP: length 46
  TOP w0.112: J13.45 v1(38.75,14.6)
  L3 w0.117: v1(16.66,38.2) 16.66,37.81 16.75,37.72 17,37.72 17.1,37.62 17.1,37.27 17.19,37.18 17.35,37.18 17.48,37.31 17.66,37.31 17.83,37.14 17.83,36.87 17.66,36.7 17.66,22.36 22.9,17.12 22.9,15.91 24.22,14.59 28.58,14.59 29.57,15.58 31.56,15.58 31.84,15.86 32.3,15.86 32.53,16.08 33.58,16.08 34.4,15.26 38.92,15.26 39,15.18 39,14.85 v1(38.75,14.6)
  BOTTOM w0.112: L20.5 16.55,38.48 16.49,38.41 16.49,38.27 16.56,38.2 v1(16.66,38.2)
MDSI_A_DATA_3_DN: length 12
  L3 w0.117: v1(15.95,40.31) 15.87,40.38 15.67,40.38 15.57,40.48 15.57,40.87 15.79,41.09 15.79,42.27 17.3,43.78 20.39,43.78 22.23,45.62 22.23,45.88 v1(22.13,45.98)
  BOTTOM w0.112: J3.76 22.25,45.34 22.25,45.87 v1(22.13,45.98) ; v1(15.95,40.31) 16.15,40.1 L20.3
MDSI_A_DATA_3_DP: length 11.9
  L3 w0.117: v1(16.55,40.32) 16.51,40.32 16.04,40.79 16.04,42.17 17.4,43.53 20.49,43.53 22.48,45.52 22.48,45.76 v1(22.73,46.02)
  BOTTOM w0.112: v1(22.73,46.02) 22.52,45.8 22.52,45.34 J3.78 ; L20.4 v1(16.55,40.32)
OTG_EN: length 28.4
  TOP w0.1: TP24.1 44.54,32.37 R61.1 44.59,32.32 44.59,28.26 46.17,26.68 47.55,26.68 48.4,25.83 48.4,23.9 46.34,21.84 42.84,21.84 41.91,20.91 41.55,20.91 v3(40.98,20.34)
  BOTTOM w0.1: J2.69 36.48,22.34 36.16,22.02 36.16,20.68 36.26,20.57 36.26,20.5 36.35,20.42 36.42,20.42 36.45,20.39 38.34,20.39 38.64,20.69 38.89,20.69 39.69,20.69 39.89,20.49 40.81,20.49 40.97,20.34 v3(40.98,20.34)
OTG_EN_R: length 1.4
  TOP w0.1: v1(43.78,32.97) R61.2 43.68,32.27 U22.4
OTG_I_ADJ: length 1.4
  TOP w0.1: U22.2 43.03,28.96 43.03,28.96 R62.1 v1(43.03,28.25)
OTG_OCFLAG_TP: length 2.1
  TOP w0.1: U22.3 44.25,29.04 TP32.1
PCIE1_CLK_DN: length 1.4
  TOP w0.112: TP7.1 v1(24.58,45.98)
  BOTTOM w0.112: TP7.1 v1(24.58,45.98)
PCIE1_CLK_DP: length 1.5
  TOP w0.112: v1(23.98,45.97) 23.97,45.96 TP6.1
  BOTTOM w0.112: v1(23.98,45.97) 24.18,45.77 J3.86
PCIE1_CLKREQ_N: length 2.2
  TOP w0.1: TP3.1 16.47,45.42 v3(17.03,45.98)
  BOTTOM w0.1: v3(17.03,45.98) 17,45.95 17,45.95 16.98,45.93 J3.50
PCIE1_PERST_N: length 2.3
  TOP w0.1: v1(20.98,46.38) 20.77,46.16 TP4.1
  BOTTOM w0.1: J3.70 v1(20.98,46.38)
PCIE1_WAKE_N: length 2
  TOP w0.1: v1(21.43,45.98) 22.13,45.28 TP5.1
  BOTTOM w0.1: v1(21.43,45.98) 21.38,45.93 J3.72
PMIC_PWRBTN_N: length 101.6
  TOP w0.1: v1(59.04,49.47) 59.02,49.45 SW2.3 59.49,48.62 ; 59.49,48.62 60.93,48.62 61.4,49.09 63.23,49.09 63.7,48.62 SW2.4 ; 59.49,48.62 59.66,48.45 CR24.1 ; J12.4 12,50.83 v1(12.01,50.82) 12.01,50.81 13.44,49.38 18.81,49.38 19.18,49.01 19.18,46.25 21.56,43.87 21.58,43.87 21.61,43.84 21.95,43.84 23.18,42.61 23.18,42.2 22.98,42 22.98,38.22 22.77,38.01 22.77,37.97 22.75,37.95 22.75,37.61 22.77,37.59 22.77,23.77 v1(24.48,22.06) 24.64,22.06
  L3 w0.1: v1(12.01,50.82) 12.41,50.42 14.17,50.42 14.57,50.82 30.7,50.82 33.94,47.58 49.33,47.58 49.87,47.04 57.17,47.04 59.04,48.91 v1(59.04,49.47)
  BOTTOM w0.1: 12.01,50.82 v1(12.01,50.82) 12.01,52.21 CR32.1 R137.2 ; v1(24.48,22.06) J2.9
PMIC_PWRGOOD: length 2.8
  TOP w0.1: TP50.1 29.28,20.97 v1(29.28,22.06)
  BOTTOM w0.1: J2.33 v1(29.28,22.06)
PMIC_RESET_N: length 2.5
  TOP w0.1: TP49.1 25.28,21.51 v1(25.28,22.06)
  BOTTOM w0.1: J2.13 v1(25.28,22.06)
PWM_2: length 41.3
  TOP w0.1: v1(40.24,40.84) 40.81,41.41 40.81,50.91 40,51.72 J12.32 ; v1(26.39,39.41) 25.69,38.71 25.69,31.3 26.43,30.56 26.43,29.38 26.88,28.93 v1(26.88,26.99)
  BOTTOM w0.1: v1(26.88,26.99) J2.22 ; v1(40.24,40.84) 40.24,39.91 39.39,39.06 35.94,39.06 35.75,38.87 27.94,38.87 27.4,39.41 v1(26.39,39.41)
PWM_3: length 36.4
  TOP w0.1: v1(26.8,38.66) 26.8,37.44 26.8,29.48 27.28,29 v1(27.28,27.44) ; v1(41.6,39.77) 41.6,45.39 41.43,45.56 41.43,45.95 41.6,46.12 41.6,47.38 J12.33
  BOTTOM w0.1: v1(26.8,38.66) 27.4,38.66 27.7,38.36 37.47,38.36 37.65,38.54 40.37,38.54 v1(41.6,39.77) ; v1(27.28,27.44) J2.24
PWRCTL_POL: length 1.9
  TOP w0.1: R65.2 v2(65.47,28.98) U2.41
PWRGOOD_1P1V: length 0.7
  TOP w0.1: 62.64,38.11 R57.2
  TOP w0.2: U5.6 62.64,38.11
PWRGOOD_3P3V: length 0.7
  TOP w0.2: U27.6 52.55,37.73 R46.2
R1_SENSE_N: length 8.1
  TOP w0.1: v1(70.95,45.97) 70.27,45.97 69.98,45.68 66.94,45.68 66.73,45.89 R1.5
  BOTTOM w0.1: J1.2 72.21,48.25 70.95,46.99 v1(70.95,45.97)
R1_SENSE_P: length 7
  TOP w0.1: v1(70.51,45.15) 70.44,45.22 66.94,45.22 66.73,45.01 R1.2
  BOTTOM w0.1: J1.1 71.83,45.15 v1(70.51,45.15)
RF_ANT_WIFI_A: length 0.7
  BOTTOM w0.43: R116.1 L24.2
RF_ANT_WIFI_B_BT: length 0.8
  BOTTOM w0.43: R124.1 L27.2
RF_CONN_WIFI_A: length 1.3
  BOTTOM w0.43: R115.1 73.66,39.36 J20.1
RF_CONN_WIFI_B_BT: length 3.4
  BOTTOM w0.43: R120.1 76.19,26.3 75.24,27.25 J21.1
RF_MATCH_WIFI_A: length 0.9
  BOTTOM w0.43: R115.2 74.54,39.36 L22.1
RF_MATCH_WIFI_A_L: length 2.3
  BOTTOM w0.43: L22.2 75.59,38.65 C85.1 76.19,38.66 L23.1 76.19,39.36 L24.1
RF_MATCH_WIFI_B_BT: length 0.6
  BOTTOM w0.43: L25.1 R120.2
RF_MATCH_WIFI_B_BT_L: length 2.3
  BOTTOM w0.43: L27.1 76.19,20.71 L26.1 C86.1 76.19,22.22 76.19,22.23
RFU_FAN: length 7.2
  TOP w0.2: TP35.1 v1(12.3,9.39)
  BOTTOM w0.35: J17.2 v1(12.3,9.39)
SDCARD_CD_N: length 32.7
  L5 w0.084: v1(11.38,21.88) 11.38,21.88 11.49,21.88 11.68,21.69 15.47,21.69 18.76,18.4 33.43,18.4 35.66,20.63 37.57,20.63 38.48,21.54 v1(38.48,22.06)
  BOTTOM w0.1: J2.79 v1(38.48,22.06)
  BOTTOM w0.201: v1(11.38,21.88) 11.38,21.88 11.41,21.85 R100.1
SDCARD_CD_N_CONN: length 8.6
  TOP w0.201: 8.06,14.09 8.06,14.66 8.92,15.52 8.92,16.24 10.11,17.43 v1(10.22,17.43)
  L5 w0.084: v1(10.22,17.43) v4(9.25,17.43)
  BOTTOM w0.201: v1(10.22,17.43) 10.74,17.43 11.2,17.89 11.2,18.41 11.41,18.62 R100.2
SDCARD_CLK: length 37.9
  L5 w0.084: v1(8.85,22.49) 10.72,22.49 11.33,23.11 14.62,23.11 18.33,19.4 28.47,19.4 28.77,19.1 31.54,19.1 32.68,20.24 34.71,20.24 35.5,21.03 37.4,21.03 37.68,21.31 v1(37.68,22.06)
  BOTTOM w0.1: J2.75 v1(37.68,22.06)
  BOTTOM w0.201: U1.C1 8.85,19.26 8.9,19.31 8.9,19.69 8.85,19.74 8.85,21.81 8.8,21.86 8.8,22.23 8.85,22.28 v1(8.85,22.49)
SDCARD_CLK_CONN: length 18.2
  TOP w0.201: v1(6.14,3.2) J5.5
  L3 w0.151: v1(6.14,3.2) 6.13,3.19 6.13,1.76 6.28,1.61 6.88,1.61 7.03,1.76 7.03,3.77 10.14,6.88 v1(10.14,13.21)
  BOTTOM w0.201: v1(10.14,13.21) 10.23,13.3 C1.1 R32.2
SDCARD_CLK_CONN_R: length 2.3
  BOTTOM w0.201: U1.C5 8.92,16.57 8.92,15.44 9.42,14.93 R32.1
SDCARD_CMD: length 38.8
  L5 w0.084: v1(40.48,22.51) 40.71,22.51 41.28,21.94 41.28,21.61 41.04,21.37 40.02,21.37 38.06,19.41 36.14,19.41 33.93,17.2 18.26,17.2 14.98,20.49 11.14,20.49 9.25,18.6 v4(9.25,17.88)
  BOTTOM w0.1: U1.D2 v4(9.25,17.88)
  BOTTOM w0.201: J2.89 v1(40.48,22.51)
